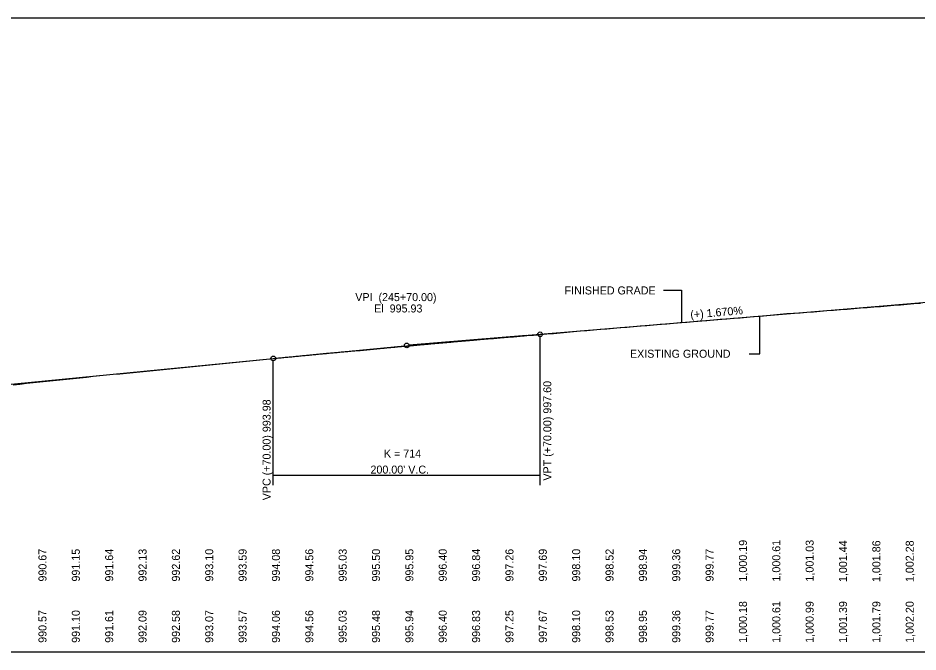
# Model space of a CAD drawing. Extents: x 4180 to 16997695, y 4 to 12629821.
# Drawn here: x 16976699 to 16977373, y 12628962 to 12629437 of the extents above; entities that cross this region are included whole.
import ezdxf

# ---------------------------------------------------------------- set-up
doc = ezdxf.new("R2010")
doc.units = 0
for name, color, linetype in [('Default', 7, 'Continuous'), ('RD_DDB_EX_Tx', 7, 'Continuous'), ('RD_DDB_GradeTX', 7, 'Continuous'), ('RD_DDB_PI', 7, 'Continuous'), ('RD_DDB_PR_Tx', 7, 'Continuous'), ('RD_DDB_Profile_EX', 7, 'Continuous'), ('RD_DDB_Profile_PR', 7, 'Continuous'), ('RD_DDB_StripGrade', 7, 'Continuous'), ('RD_DDB_StripGrade_PR', 7, 'Continuous'), ('RD_DDB_VCLbl', 7, 'Continuous')]:
    doc.layers.add(name, color=color, linetype=linetype)

msp = doc.modelspace()

# ---------------------------------------------------------------- linework, layer by layer
at = {"layer": 'Default'}
msp.add_lwpolyline([(16976219.88, 12628961.61), (16977719.88, 12628961.61), (16977719.88, 12629436.61), (16976219.88, 12629436.61)], close=True, dxfattribs=at)
at = {"layer": 'RD_DDB_EX_Tx'}
for p, q in [((16977254.64, 12629185.06), (16977254.64, 12629213.27)), ((16977246.43, 12629185.06), (16977254.64, 12629185.06))]:
    msp.add_line(p, q, dxfattribs=at)
at = {"layer": 'RD_DDB_PI'}
for p, q in [((16977079.56, 12629198.76), (16976991.62, 12629191.42)), ((16976900.3, 12629182.54), (16976988.13, 12629191.1))]:
    msp.add_line(p, q, dxfattribs=at)
msp.add_circle((16976989.88, 12629191.27), 1.75, dxfattribs=at)
at = {"layer": 'RD_DDB_PR_Tx'}
for p, q in [((16977182.42, 12629232.7), (16977195.83, 12629232.7)), ((16977195.83, 12629232.7), (16977195.83, 12629208.47))]:
    msp.add_line(p, q, dxfattribs=at)
at = {"layer": 'RD_DDB_Profile_EX'}
for points in [[(16977119.88, 12629202.12), (16977124.88, 12629202.57), (16977129.88, 12629202.99), (16977134.88, 12629203.41), (16977139.88, 12629203.83), (16977144.88, 12629204.25), (16977149.88, 12629204.67), (16977154.88, 12629205.09), (16977159.88, 12629205.51), (16977164.88, 12629205.93), (16977169.88, 12629206.35), (16977174.88, 12629206.76), (16977179.88, 12629207.18), (16977184.88, 12629207.6), (16977189.88, 12629208.01), (16977194.88, 12629208.43), (16977199.88, 12629208.85), (16977204.88, 12629209.26), (16977209.88, 12629209.66), (16977214.88, 12629210.06), (16977219.88, 12629210.46), (16977224.88, 12629210.86), (16977229.88, 12629211.26), (16977234.88, 12629211.67), (16977239.88, 12629212.09), (16977244.88, 12629212.5), (16977249.88, 12629212.91), (16977254.88, 12629213.31), (16977259.88, 12629213.72), (16977264.88, 12629214.18), (16977269.88, 12629214.65), (16977274.88, 12629215.1), (16977279.88, 12629215.45), (16977284.88, 12629215.8), (16977289.88, 12629216.15), (16977294.88, 12629216.54), (16977299.88, 12629216.95), (16977304.88, 12629217.35), (16977309.88, 12629217.76), (16977314.88, 12629218.16), (16977319.88, 12629218.56), (16977324.88, 12629218.97), (16977329.88, 12629219.37), (16977334.88, 12629219.77), (16977339.88, 12629220.18), (16977344.88, 12629220.58), (16977349.88, 12629220.98), (16977354.88, 12629221.39), (16977359.88, 12629221.79), (16977364.88, 12629222.19), (16977369.88, 12629222.62), (16977374.88, 12629223.08)], [(16976694.88, 12629161.85), (16976699.88, 12629162.37), (16976704.88, 12629162.9), (16976709.88, 12629163.43), (16976714.88, 12629163.95), (16976719.88, 12629164.48), (16976724.88, 12629165), (16976729.88, 12629165.53), (16976734.88, 12629166.05), (16976739.88, 12629166.58), (16976744.88, 12629167.1), (16976749.88, 12629167.63), (16976754.88, 12629168.15), (16976759.88, 12629168.66), (16976764.88, 12629169.16), (16976769.88, 12629169.65), (16976774.88, 12629170.14), (16976779.88, 12629170.62), (16976784.88, 12629171.11), (16976789.88, 12629171.6), (16976794.88, 12629172.08), (16976799.88, 12629172.57), (16976804.88, 12629173.05), (16976809.88, 12629173.54), (16976814.88, 12629174.03), (16976819.88, 12629174.51), (16976824.88, 12629175), (16976829.88, 12629175.48), (16976834.88, 12629175.97), (16976839.88, 12629176.45), (16976844.88, 12629176.96), (16976849.88, 12629177.46), (16976854.88, 12629177.96), (16976859.88, 12629178.45), (16976864.88, 12629178.95), (16976869.88, 12629179.44), (16976874.88, 12629179.94), (16976879.88, 12629180.43), (16976884.88, 12629180.93), (16976889.88, 12629181.42), (16976894.88, 12629181.92), (16976899.88, 12629182.41), (16976904.88, 12629182.91), (16976909.88, 12629183.4), (16976914.88, 12629183.9), (16976919.88, 12629184.39), (16976924.88, 12629184.88), (16976929.88, 12629185.38), (16976934.88, 12629185.87), (16976939.88, 12629186.33), (16976944.88, 12629186.75), (16976949.88, 12629187.18), (16976954.88, 12629187.6), (16976959.88, 12629188.07), (16976964.88, 12629188.53), (16976969.88, 12629189), (16976974.88, 12629189.46), (16976979.88, 12629189.93), (16976984.88, 12629190.39), (16976989.88, 12629190.86), (16976994.88, 12629191.32), (16976999.88, 12629191.78), (16977004.88, 12629192.23), (16977009.88, 12629192.68), (16977014.88, 12629193.13), (16977019.88, 12629193.59), (16977024.88, 12629194.05), (16977029.88, 12629194.49), (16977034.88, 12629194.91), (16977039.88, 12629195.33), (16977044.88, 12629195.75), (16977049.88, 12629196.17), (16977054.88, 12629196.59), (16977059.88, 12629197.01), (16977064.88, 12629197.43), (16977069.88, 12629197.85), (16977074.88, 12629198.27), (16977079.88, 12629198.69), (16977084.88, 12629199.11), (16977089.88, 12629199.53), (16977094.88, 12629199.95), (16977099.88, 12629200.36), (16977104.88, 12629200.78), (16977109.88, 12629201.22), (16977114.88, 12629201.67), (16977119.88, 12629202.12)]]:
    msp.add_lwpolyline(points, dxfattribs=at)
at = {"layer": 'RD_DDB_Profile_PR'}
for p, q in [((16977319.88, 12629218.83), (16977499.88, 12629233.86)), ((16977089.88, 12629199.62), (16977319.88, 12629218.83)), ((16976164.88, 12629110.83), (16976889.88, 12629181.52))]:
    msp.add_line(p, q, dxfattribs=at)
msp.add_spline([(16976889.88, 12629181.52), (16976893.88, 12629181.91), (16976897.88, 12629182.3), (16976901.88, 12629182.68), (16976905.88, 12629183.07), (16976909.88, 12629183.46), (16976913.88, 12629183.84), (16976917.88, 12629184.22), (16976921.88, 12629184.6), (16976925.88, 12629184.98), (16976929.88, 12629185.36), (16976933.88, 12629185.74), (16976937.88, 12629186.12), (16976941.88, 12629186.5), (16976945.88, 12629186.87), (16976949.88, 12629187.24), (16976953.88, 12629187.62), (16976957.88, 12629187.99), (16976961.88, 12629188.36), (16976965.88, 12629188.73), (16976969.88, 12629189.1), (16976973.88, 12629189.46), (16976977.88, 12629189.83), (16976981.88, 12629190.19), (16976985.88, 12629190.56), (16976989.88, 12629190.92), (16976993.88, 12629191.28), (16976997.88, 12629191.64), (16977001.88, 12629192), (16977005.88, 12629192.36), (16977009.88, 12629192.72), (16977013.88, 12629193.07), (16977017.88, 12629193.43), (16977021.88, 12629193.78), (16977025.88, 12629194.13), (16977029.88, 12629194.48), (16977033.88, 12629194.83), (16977037.88, 12629195.18), (16977041.88, 12629195.53), (16977045.88, 12629195.88), (16977049.88, 12629196.22), (16977053.88, 12629196.57), (16977057.88, 12629196.91), (16977061.88, 12629197.25), (16977065.88, 12629197.6), (16977069.88, 12629197.94), (16977073.88, 12629198.28), (16977077.88, 12629198.61), (16977081.88, 12629198.95), (16977085.88, 12629199.29), (16977089.88, 12629199.62)], degree=3, dxfattribs=at)
at = {"layer": 'RD_DDB_VCLbl'}
for p, q in [((16977089.88, 12629086.52), (16977089.88, 12629197.87)), ((16976889.88, 12629086.52), (16976889.88, 12629179.77)), ((16976889.88, 12629094.02), (16977089.88, 12629094.02))]:
    msp.add_line(p, q, dxfattribs=at)
for centre in [(16977089.88, 12629199.62), (16976889.88, 12629181.52)]:
    msp.add_circle(centre, 1.75, dxfattribs=at)

# ---------------------------------------------------------------- texts
at = {"layer": 'RD_DDB_EX_Tx'}
msp.add_text('EXISTING GROUND', height=6, dxfattribs=at).set_placement((16977157.21, 12629182.07))
at = {"layer": 'RD_DDB_GradeTX'}
msp.add_text('(+) 1.670%', height=6, rotation=4.77317, dxfattribs=at).set_placement((16977202.71, 12629211.38))
at = {"layer": 'RD_DDB_PI'}
for s, p in [('VPI  (245+70.00)', (16976951.34, 12629224.51)), ('El  995.93', (16976965.51, 12629216.01))]:
    msp.add_text(s, height=6, dxfattribs=at).set_placement(p)
at = {"layer": 'RD_DDB_PR_Tx'}
msp.add_text('FINISHED GRADE', height=6, dxfattribs=at).set_placement((16977108.23, 12629229.5))
at = {"layer": 'RD_DDB_StripGrade'}
for s, p in [('1,000.18', (16977244.88, 12628968.48)), ('1,000.61', (16977269.88, 12628968.48)), ('1,000.99', (16977294.88, 12628968.48)), ('1,001.39', (16977319.88, 12628968.48)), ('1,001.79', (16977344.88, 12628968.48)), ('1,002.20', (16977369.88, 12628968.48)), ('990.57', (16976719.88, 12628968.48)), ('991.10', (16976744.88, 12628968.48)), ('991.61', (16976769.88, 12628968.48)), ('992.09', (16976794.88, 12628968.48)), ('992.58', (16976819.88, 12628968.48)), ('993.07', (16976844.88, 12628968.48)), ('993.57', (16976869.88, 12628968.48)), ('994.06', (16976894.88, 12628968.48)), ('994.56', (16976919.88, 12628968.48)), ('995.03', (16976944.88, 12628968.48)), ('995.48', (16976969.88, 12628968.48)), ('995.94', (16976994.88, 12628968.48)), ('996.40', (16977019.88, 12628968.48)), ('996.83', (16977044.88, 12628968.48)), ('997.25', (16977069.88, 12628968.48)), ('997.67', (16977094.88, 12628968.48)), ('998.10', (16977119.88, 12628968.48)), ('998.53', (16977144.88, 12628968.48)), ('998.95', (16977169.88, 12628968.48)), ('999.36', (16977194.88, 12628968.48)), ('999.77', (16977219.88, 12628968.48))]:
    msp.add_text(s, height=6, rotation=90, dxfattribs=at).set_placement(p)
at = {"layer": 'RD_DDB_StripGrade_PR'}
for s, p in [('1,000.19', (16977244.88, 12629014.4)), ('1,000.61', (16977269.88, 12629014.4)), ('1,001.03', (16977294.88, 12629014.4)), ('1,001.44', (16977319.88, 12629013.99)), ('1,001.86', (16977344.88, 12629013.99)), ('1,002.28', (16977369.88, 12629013.99)), ('990.67', (16976719.88, 12629014.4)), ('991.15', (16976744.88, 12629014.4)), ('991.64', (16976769.88, 12629014.4)), ('992.13', (16976794.88, 12629014.4)), ('992.62', (16976819.88, 12629014.4)), ('993.10', (16976844.88, 12629014.4)), ('993.59', (16976869.88, 12629014.4)), ('994.08', (16976894.88, 12629014.4)), ('994.56', (16976919.88, 12629014.4)), ('995.03', (16976944.88, 12629014.4)), ('995.50', (16976969.88, 12629014.4)), ('995.95', (16976994.88, 12629014.4)), ('996.40', (16977019.88, 12629014.4)), ('996.84', (16977044.88, 12629014.4)), ('997.26', (16977069.88, 12629014.4)), ('997.69', (16977094.88, 12629014.4)), ('998.10', (16977119.88, 12629014.4)), ('998.52', (16977144.88, 12629014.4)), ('998.94', (16977169.88, 12629014.4)), ('999.36', (16977194.88, 12629014.4)), ('999.77', (16977219.88, 12629014.4))]:
    msp.add_text(s, height=6, rotation=90, dxfattribs=at).set_placement(p)
at = {"layer": 'RD_DDB_VCLbl'}
for s, p in [('VPT (+70.00) 997.60', (16977098.25, 12629090)), ('VPC (+70.00) 993.98', (16976887.88, 12629075.27))]:
    msp.add_text(s, height=6, rotation=90, dxfattribs=at).set_placement(p)
for s, p in [('K = 714', (16976972.81, 12629107.27)), ("200.00' V.C.", (16976962.74, 12629095.27))]:
    msp.add_text(s, height=6, dxfattribs=at).set_placement(p)

doc.saveas('drawing.dxf')
